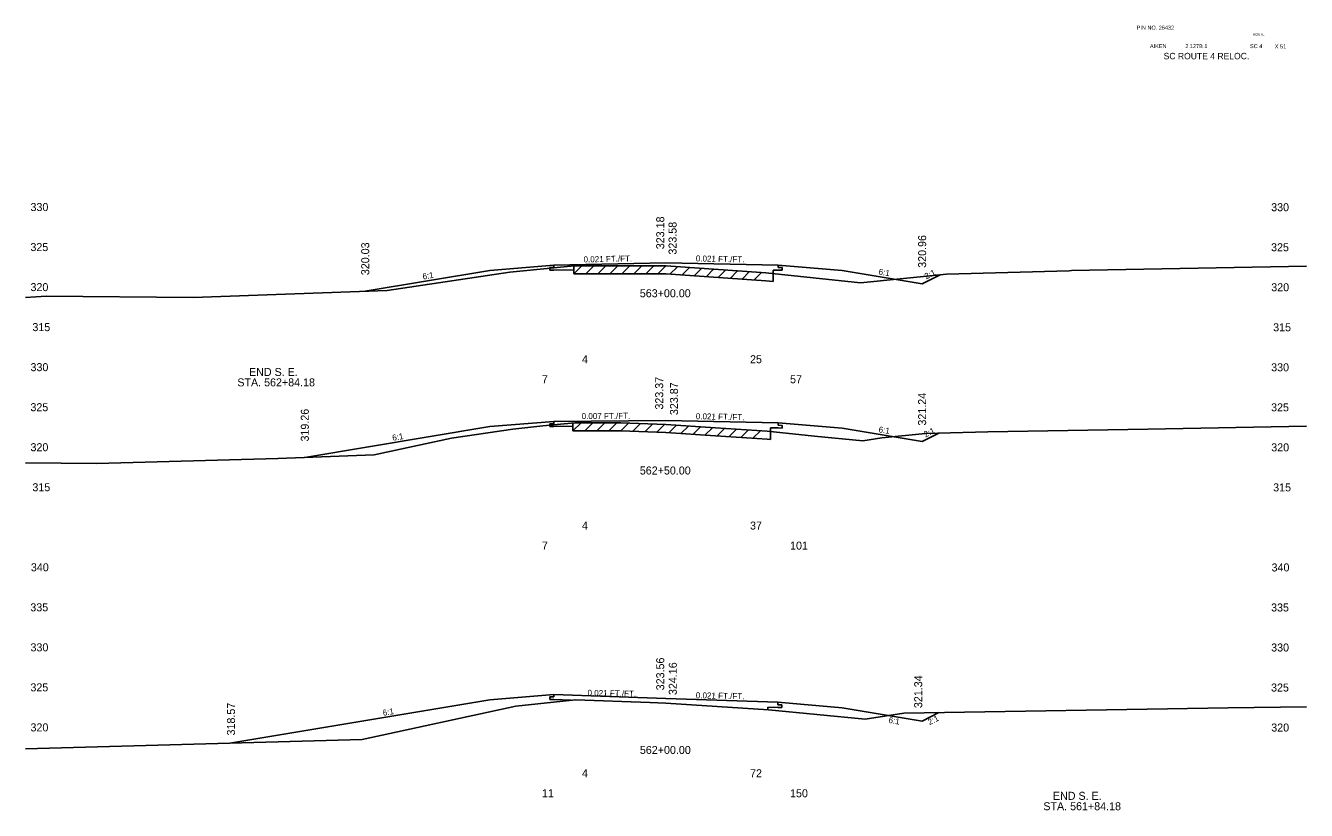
# Model space of a CAD drawing. Extents: x 2967 to 4323, y -3677 to -817.
# Drawn here: x 4005.3 to 4165.3, y -3674.7 to -3576.6 of the extents above; entities that cross this region are included whole.
import ezdxf

# ---------------------------------------------------------------- set-up
doc = ezdxf.new("R2010")
doc.units = 0
for name, color, linetype in [('Level 1', 7, 'Continuous'), ('Level 10', 7, 'Continuous'), ('Level 11', 7, 'Continuous'), ('Level 12', 7, 'Continuous'), ('Level 20', 7, 'Continuous'), ('Level 3', 7, 'Continuous'), ('Level 32', 7, 'Continuous'), ('Level 33', 7, 'Continuous'), ('Level 59', 7, 'Continuous'), ('Level 6', 7, 'Continuous'), ('Level 60', 7, 'Continuous'), ('Level 61', 7, 'Continuous'), ('Level 7', 7, 'Continuous')]:
    doc.layers.add(name, color=color, linetype=linetype)

msp = doc.modelspace()

# ---------------------------------------------------------------- linework, layer by layer
at = {"layer": 'Level 11'}
for p, q in [((4071.26, -3606.85), (4070.76, -3606.86)), ((4070.76, -3606.86), (4070.76, -3607.2)), ((4070.76, -3607.2), (4071.26, -3607.19)), ((4071.26, -3606.55), (4071.26, -3606.85)), ((4099.26, -3606.85), (4099.26, -3606.55)), ((4099.76, -3606.86), (4099.26, -3606.85)), ((4099.26, -3607.19), (4099.76, -3607.2)), ((4099.76, -3607.2), (4099.76, -3606.86)), ((4071.26, -3626.37), (4070.76, -3626.37)), ((4070.76, -3626.37), (4070.76, -3626.71)), ((4070.76, -3626.71), (4071.26, -3626.71)), ((4071.26, -3626.07), (4071.26, -3626.37)), ((4099.26, -3626.56), (4099.26, -3626.26)), ((4099.76, -3626.58), (4099.26, -3626.56)), ((4099.26, -3626.9), (4099.76, -3626.92)), ((4099.76, -3626.92), (4099.76, -3626.58)), ((4071.25, -3660.49), (4070.75, -3660.47)), ((4070.75, -3660.47), (4070.75, -3660.81)), ((4071.25, -3660.19), (4071.25, -3660.49)), ((4070.75, -3660.81), (4071.25, -3660.83)), ((4099.25, -3661.47), (4099.25, -3661.17)), ((4099.75, -3661.49), (4099.25, -3661.47)), ((4099.25, -3661.81), (4099.75, -3661.83)), ((4099.75, -3661.83), (4099.75, -3661.49))]:
    msp.add_line(p, q, dxfattribs=at)
at = {"layer": 'Level 12'}
for p, q in [((4073.76, -3607.14), (4071.26, -3607.19)), ((4073.76, -3606.64), (4073.76, -3607.14)), ((4098.64, -3607.61), (4098.64, -3607.18)), ((4098.64, -3607.18), (4099.26, -3607.19)), ((4073.62, -3626.69), (4071.26, -3626.71)), ((4073.62, -3626.26), (4073.62, -3626.69)), ((4098.32, -3627.34), (4098.32, -3626.89)), ((4098.32, -3626.89), (4099.26, -3626.9)), ((4073.36, -3660.91), (4071.25, -3660.83)), ((4097.98, -3661.77), (4099.25, -3661.81)), ((4097.98, -3662.08), (4097.98, -3661.77))]:
    msp.add_line(p, q, dxfattribs=at)
at = {"layer": 'Level 59'}
for p, q in [((4071.26, -3606.55), (4085.26, -3606.26)), ((4085.26, -3606.26), (4099.26, -3606.55)), ((4071.26, -3626.07), (4085.26, -3625.97)), ((4085.26, -3625.97), (4099.26, -3626.26)), ((4071.25, -3660.19), (4085.26, -3660.68)), ((4085.26, -3660.68), (4099.25, -3661.17))]:
    msp.add_line(p, q, dxfattribs=at)
at = {"layer": 'Level 6'}
for p, q in [((4063.26, -3607.22), (4071.26, -3606.55)), ((4099.26, -3606.55), (4107.26, -3607.22)), ((4063.26, -3626.73), (4071.26, -3626.07)), ((4099.26, -3626.26), (4107.26, -3626.93)), ((4063.25, -3660.86), (4071.25, -3660.19)), ((4099.25, -3661.17), (4107.25, -3661.84))]:
    msp.add_line(p, q, dxfattribs=at)
at = {"layer": 'Level 60'}
for p, q in [((4050.41, -3609.72), (4065.77, -3607.42)), ((4065.77, -3607.42), (4073.79, -3606.64)), ((4073.79, -3606.64), (4083.49, -3606.66)), ((4083.49, -3606.66), (4085.27, -3606.66)), ((4085.27, -3606.66), (4097.74, -3607.51)), ((4097.74, -3607.51), (4109.57, -3608.77)), ((4109.57, -3608.77), (4120.32, -3607.67)), ((4120.32, -3607.67), (4135.62, -3607.25)), ((4135.62, -3607.25), (4135.92, -3607.24)), ((4135.92, -3607.24), (4165.26, -3606.68)), ((4005.26, -3610.58), (4007.84, -3610.44)), ((4007.84, -3610.44), (4026.18, -3610.59)), ((4026.18, -3610.59), (4050.41, -3609.72)), ((4058.46, -3628.18), (4066.13, -3627.04)), ((4066.13, -3627.04), (4069.87, -3626.63)), ((4069.87, -3626.63), (4073.88, -3626.24)), ((4073.88, -3626.24), (4079.6, -3626.25)), ((4079.6, -3626.25), (4085.26, -3626.47)), ((4085.26, -3626.47), (4091.44, -3626.89)), ((4091.44, -3626.89), (4097.89, -3627.3)), ((4125.46, -3627.39), (4145.44, -3627.06)), ((4145.44, -3627.06), (4165.26, -3626.68)), ((4048.82, -3630.27), (4058.46, -3628.18)), ((4097.89, -3627.3), (4103.83, -3627.93)), ((4103.83, -3627.93), (4109.84, -3628.51)), ((4109.84, -3628.51), (4112.24, -3628.15)), ((4112.24, -3628.15), (4117.68, -3627.6)), ((4117.68, -3627.6), (4125.46, -3627.39)), ((4036.76, -3630.71), (4048.82, -3630.27)), ((4005.26, -3631.24), (4014.16, -3631.32)), ((4014.16, -3631.32), (4036.76, -3630.71)), ((4047.31, -3665.82), (4066.49, -3661.65)), ((4066.49, -3661.65), (4073.96, -3660.84)), ((4073.96, -3660.84), (4083.26, -3661.2)), ((4083.26, -3661.2), (4085.26, -3661.28)), ((4085.26, -3661.28), (4098.07, -3662.09)), ((4098.07, -3662.09), (4110.13, -3663.26)), ((4114.99, -3662.52), (4155.51, -3661.86)), ((4155.51, -3661.86), (4165.26, -3661.74)), ((4110.13, -3663.26), (4114.99, -3662.52)), ((4005.26, -3666.96), (4047.31, -3665.82))]:
    msp.add_line(p, q, dxfattribs=at)
at = {"layer": 'Level 61'}
for p, q in [((4074.76, -3606.64), (4073.76, -3607.64)), ((4073.76, -3606.64), (4073.76, -3607.64)), ((4073.76, -3607.64), (4073.79, -3607.64)), ((4073.79, -3607.64), (4083.49, -3607.66)), ((4076.26, -3606.65), (4075.26, -3607.64)), ((4077.76, -3606.65), (4076.76, -3607.65)), ((4079.26, -3606.65), (4078.26, -3607.65)), ((4080.76, -3606.65), (4079.76, -3607.65)), ((4082.26, -3606.66), (4081.26, -3607.65)), ((4083.76, -3606.66), (4082.76, -3607.66)), ((4083.49, -3607.66), (4085.27, -3607.66)), ((4085.26, -3606.66), (4084.26, -3607.66)), ((4085.27, -3607.66), (4097.74, -3608.51)), ((4086.69, -3606.76), (4085.76, -3607.7)), ((4088.19, -3606.86), (4087.26, -3607.8)), ((4089.69, -3606.96), (4088.76, -3607.9)), ((4091.19, -3607.07), (4090.26, -3608)), ((4092.69, -3607.17), (4091.76, -3608.1)), ((4094.19, -3607.27), (4093.26, -3608.21)), ((4095.69, -3607.37), (4094.76, -3608.31)), ((4097.19, -3607.48), (4096.26, -3608.41)), ((4098.64, -3608.61), (4098.64, -3607.61)), ((4097.74, -3608.51), (4098.64, -3608.61)), ((4074.65, -3626.24), (4073.62, -3627.26)), ((4073.62, -3626.26), (4073.62, -3627.26)), ((4076.12, -3626.24), (4075.12, -3627.24)), ((4077.62, -3626.25), (4076.62, -3627.25)), ((4079.12, -3626.25), (4078.12, -3627.25)), ((4080.59, -3626.29), (4079.62, -3627.25)), ((4082.09, -3626.35), (4081.12, -3627.31)), ((4083.59, -3626.41), (4082.62, -3627.37)), ((4085.09, -3626.47), (4084.12, -3627.43)), ((4086.56, -3626.56), (4085.62, -3627.5)), ((4088.06, -3626.66), (4087.12, -3627.6)), ((4089.56, -3626.77), (4088.62, -3627.7)), ((4091.06, -3626.87), (4090.12, -3627.8)), ((4092.57, -3626.96), (4091.62, -3627.91)), ((4094.07, -3627.06), (4093.12, -3628)), ((4095.57, -3627.15), (4094.62, -3628.09)), ((4073.62, -3627.26), (4073.88, -3627.24)), ((4073.88, -3627.24), (4079.6, -3627.25)), ((4079.6, -3627.25), (4085.26, -3627.47)), ((4085.26, -3627.47), (4091.44, -3627.89)), ((4091.44, -3627.89), (4097.89, -3628.3)), ((4097.07, -3627.25), (4096.12, -3628.19)), ((4097.89, -3628.3), (4098.32, -3628.34)), ((4098.32, -3628.34), (4098.32, -3627.34))]:
    msp.add_line(p, q, dxfattribs=at)
at = {"layer": 'Level 7'}
for p, q in [((4047.69, -3609.81), (4063.26, -3607.22)), ((4107.26, -3607.22), (4117.26, -3608.89)), ((4117.26, -3608.89), (4119.53, -3607.75)), ((4040.14, -3630.59), (4063.26, -3626.73)), ((4107.26, -3626.93), (4117.26, -3628.6)), ((4117.26, -3628.6), (4119.35, -3627.55)), ((4030.79, -3666.27), (4063.25, -3660.86)), ((4107.25, -3661.84), (4117.25, -3663.51)), ((4117.25, -3663.51), (4119.36, -3662.45))]:
    msp.add_line(p, q, dxfattribs=at)

# ---------------------------------------------------------------- texts
at = {"layer": 'Level 1'}
for s, p in [('4', (4074.76, -3618.81)), ('25', (4095.76, -3618.81)), ('STA. 562+84.18', (4031.71, -3621.7)), ('END S. E.', (4033.17, -3620.4)), ('7', (4069.76, -3621.31)), ('57', (4100.76, -3621.31)), ('4', (4074.76, -3639.59)), ('37', (4095.76, -3639.59)), ('7', (4069.76, -3642.09)), ('101', (4100.76, -3642.09)), ('4', (4074.76, -3670.53)), ('72', (4095.76, -3670.53)), ('11', (4069.76, -3673.03)), ('150', (4100.76, -3673.03)), ('END S. E.', (4133.6, -3673.35)), ('STA. 561+84.18', (4132.4, -3674.65))]:
    msp.add_text(s, height=1, dxfattribs=at).set_placement(p)
at = {"layer": 'Level 10'}
for s, p in [('323.18', (4085.04, -3604.57)), ('323.37', (4084.91, -3624.6)), ('323.56', (4085.04, -3659.67))]:
    msp.add_text(s, height=1, rotation=90, dxfattribs=at).set_placement(p)
for s, p in [('563+00.00', (4081.99, -3610.57)), ('562+50.00', (4081.99, -3632.71)), ('562+00.00', (4082, -3667.62))]:
    msp.add_text(s, height=1, dxfattribs=at).set_placement(p)
at = {"layer": 'Level 20'}
for s, height, p in [('PIN NO. 26432', 0.5, (4144.06, -3577.14)), ('ROUTE', 0.3, (4158.59, -3577.88)), ('AIKEN', 0.5, (4145.72, -3579.45)), (' 2.127B.1', 0.5, (4149.94, -3579.45)), ('SC 4', 0.5, (4158.22, -3579.45)), ('X 51', 0.5, (4161.32, -3579.48)), ('SC ROUTE 4 RELOC.', 0.8, (4147.43, -3580.84))]:
    msp.add_text(s, height=height, dxfattribs=at).set_placement(p)
at = {"layer": 'Level 3'}
for s, p in [(' 330', (4005.5, -3599.8)), (' 330', (4160.49, -3599.82)), (' 325', (4005.49, -3604.8)), (' 325', (4160.48, -3604.82)), (' 320', (4005.5, -3609.8)), (' 320', (4160.5, -3609.82)), (' 315', (4005.74, -3614.8)), (' 315', (4160.74, -3614.82)), (' 330', (4005.5, -3619.8)), (' 330', (4160.49, -3619.82)), (' 325', (4005.49, -3624.8)), (' 325', (4160.48, -3624.82)), (' 320', (4005.5, -3629.8)), (' 320', (4160.5, -3629.82)), (' 315', (4005.74, -3634.8)), (' 315', (4160.74, -3634.82)), (' 340', (4005.55, -3644.8)), (' 340', (4160.54, -3644.82)), (' 335', (4005.48, -3649.8)), (' 335', (4160.48, -3649.82)), (' 330', (4005.5, -3654.8)), (' 330', (4160.49, -3654.82)), (' 325', (4005.49, -3659.8)), (' 325', (4160.48, -3659.82)), (' 320', (4005.5, -3664.8)), (' 320', (4160.5, -3664.82))]:
    msp.add_text(s, height=1, dxfattribs=at).set_placement(p)
at = {"layer": 'Level 32'}
for s, rotation, p in [('0.021 FT./FT.', 1.1916, (4074.97, -3606.22)), ('0.021 FT./FT.', 358.8084, (4088.98, -3606.09)), ('6:1', 9.4623, (4054.91, -3608.36)), ('6:1', 350.5377, (4111.78, -3607.72)), ('2:1', 26.5651, (4117.78, -3608.35)), ('0.007 FT./FT.', 0.3773, (4074.73, -3625.79)), ('0.021 FT./FT.', 358.8084, (4088.98, -3625.8)), ('6:1', 350.5377, (4111.78, -3627.43)), ('2:1', 26.5651, (4117.69, -3628.1)), ('6:1', 9.4623, (4051.13, -3628.5)), ('0.021 FT./FT.', 358.8084, (4075.45, -3660.35)), ('0.021 FT./FT.', 358.8084, (4088.98, -3660.66)), ('6:1', 9.4623, (4049.94, -3662.86)), ('6:1', 350.5377, (4113.02, -3663.73)), ('2:1', 26.5651, (4118.19, -3664.03))]:
    msp.add_text(s, height=0.75, rotation=rotation, dxfattribs=at).set_placement(p)
at = {"layer": 'Level 33'}
for s, p in [('320.96', (4117.76, -3606.89)), ('320.03', (4048.19, -3607.81)), ('321.24', (4117.76, -3626.6)), ('319.26', (4040.64, -3628.59)), ('321.34', (4117.27, -3661.89)), ('318.57', (4031.42, -3665.31))]:
    msp.add_text(s, height=1, rotation=90, dxfattribs=at).set_placement(p)
at = {"layer": 'Level 59'}
for s, p in [(' 323.58', (4086.58, -3605.61)), (' 323.87', (4086.76, -3625.66)), (' 324.16', (4086.61, -3660.63))]:
    msp.add_text(s, height=1, rotation=90, dxfattribs=at).set_placement(p)

doc.saveas('drawing.dxf')
